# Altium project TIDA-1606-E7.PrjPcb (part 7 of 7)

## Sheet TIDA-1606-Aux-Supply-E7.SchDoc
size 431 x 279 mm; Date: Not shown in title block; ApprovedBy: Not shown in title block; CheckedBy: Not shown in title block; Author: Not shown in title block; CompanyName: Not shown in title block; Engineer: Not shown in title block; Organization: Not shown in title block; Address1: Not shown in title block; Address2: Not shown in title block; Address3: Not shown in title block; Address4: Not shown in title block; DocumentNumber: 3; Revision: Use project parameter SCH_Rev; SheetNumber: 3; SheetTotal: 16; PageSetup: Record=PageOptions¦CenterHorizontal=True¦CenterVertical=True¦PrintScale=1.00¦XCorrection=1.00¦YCorrection=1.00¦PrintKind=0¦BorderSize=5000000¦LeftOffset=0¦BottomOffset=0¦Orientation=2¦PaperLength=1000¦PaperWidth=1000¦Scale=100¦PaperSource=15¦PrintQuality=600¦MediaType=1¦DitherType=10¦PaperKind=Letter¦PrintScaleMode=1
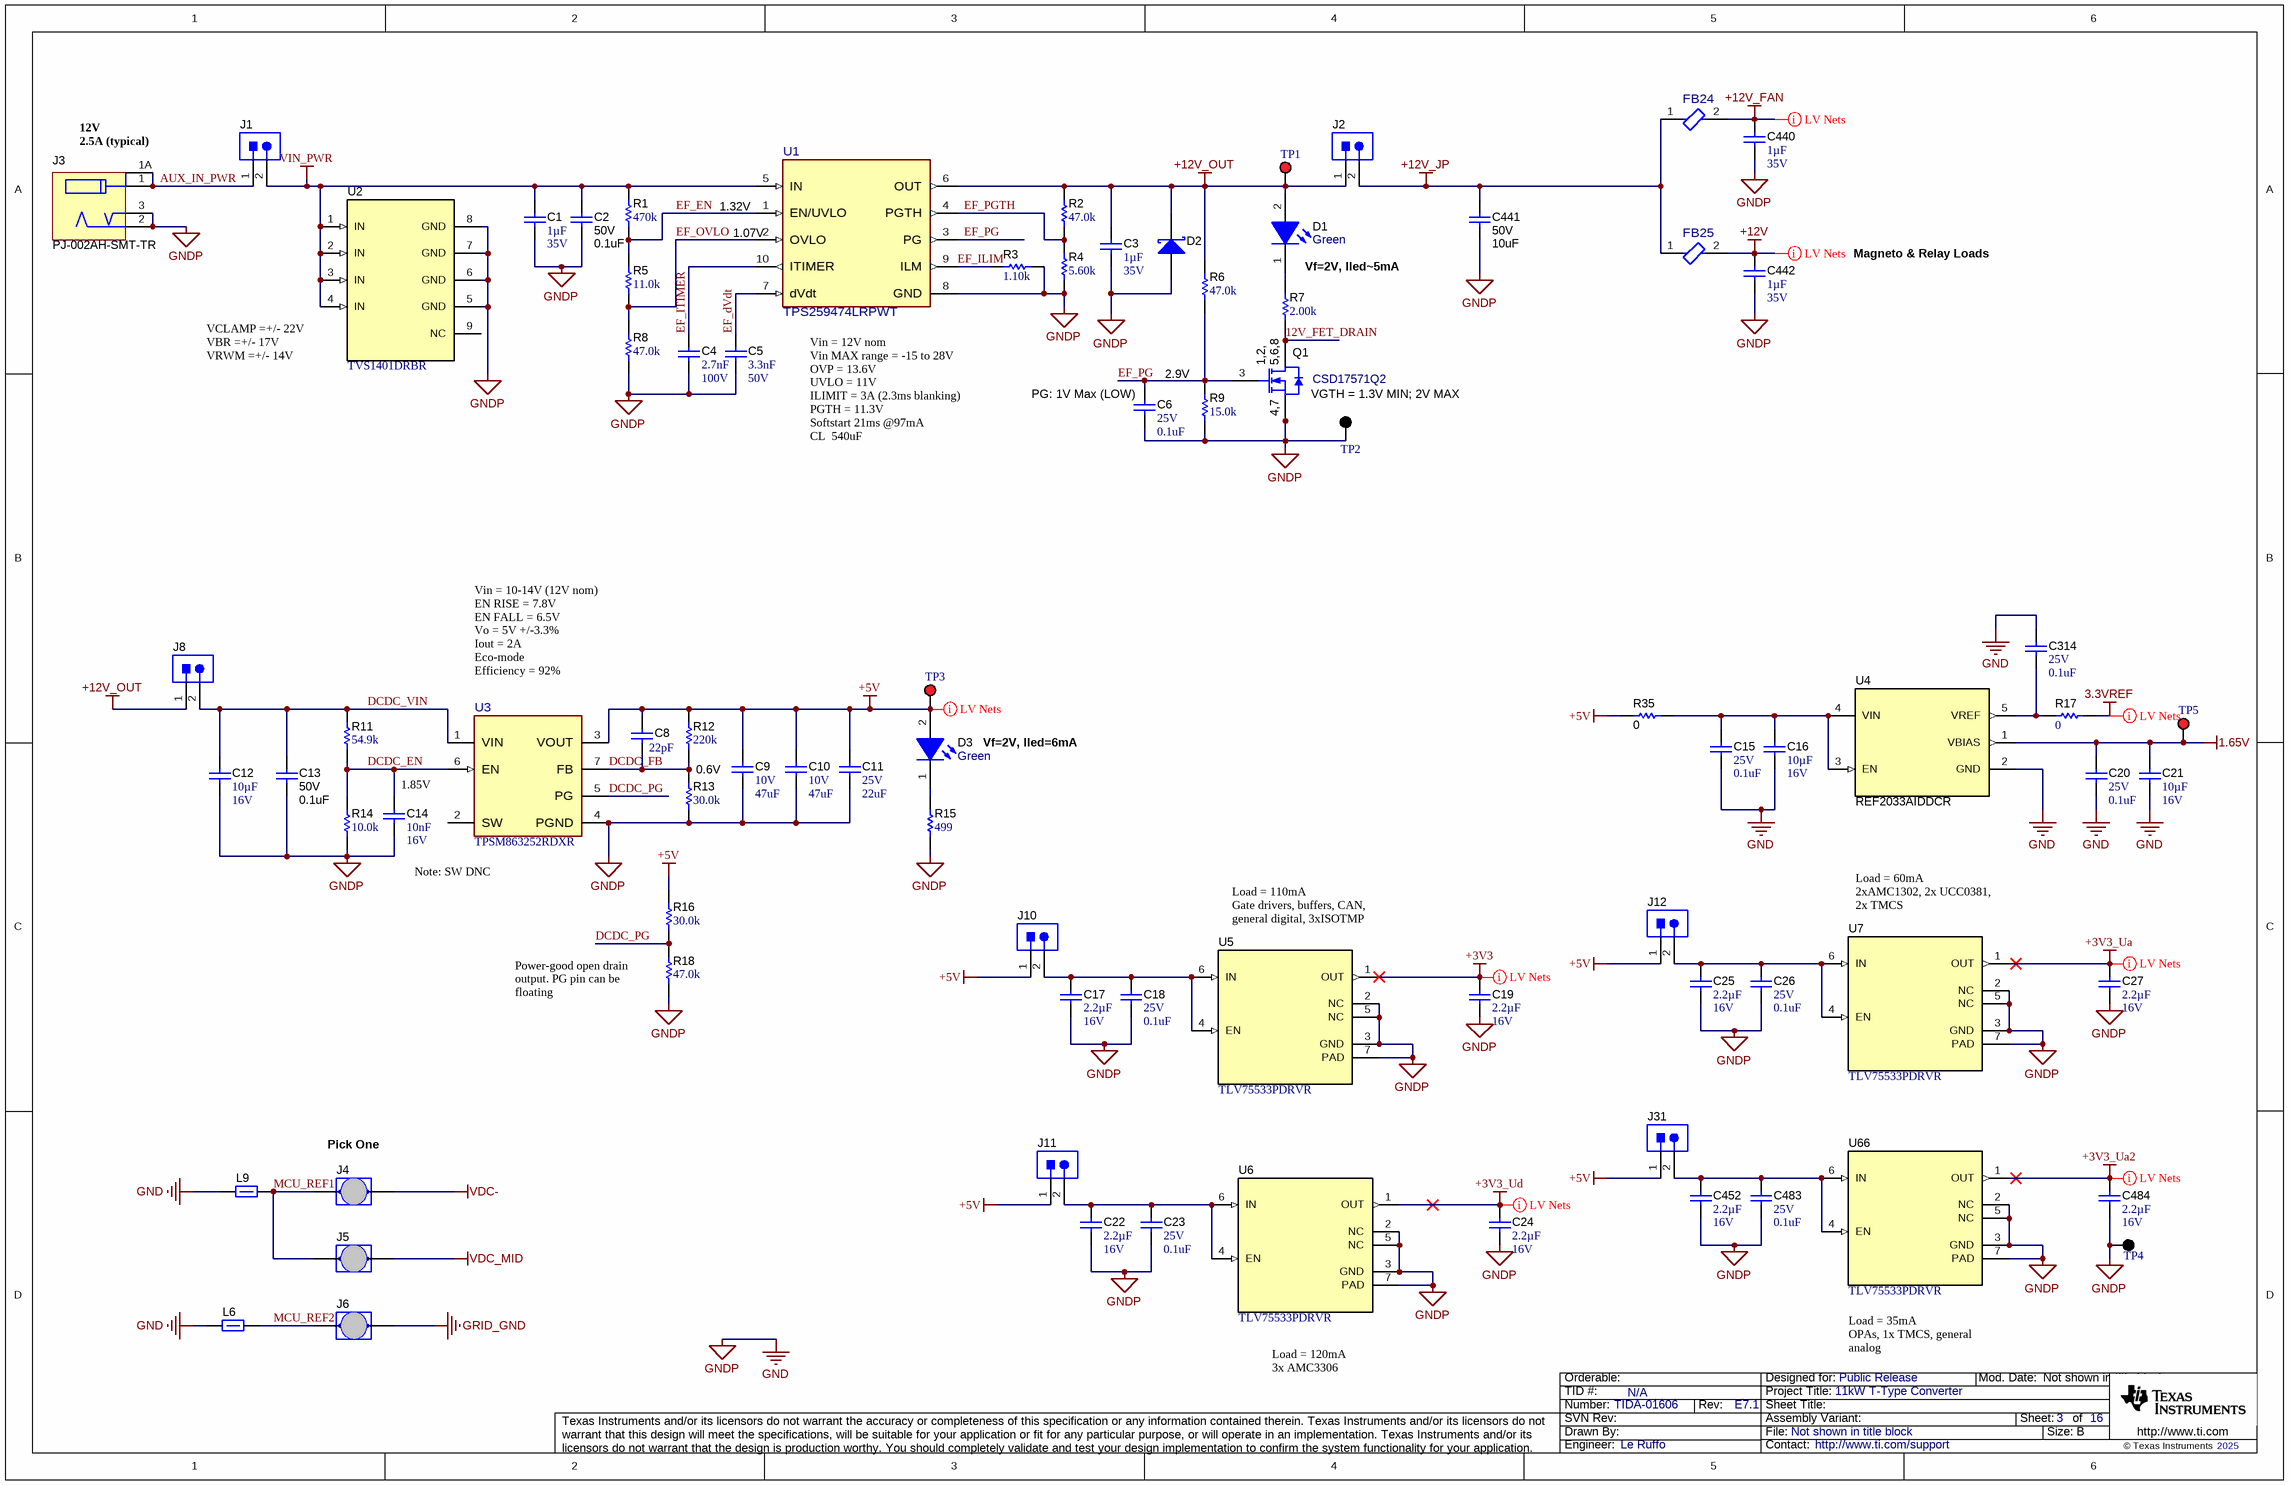
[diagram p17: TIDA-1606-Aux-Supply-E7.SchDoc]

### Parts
C1  Cap_F: 1µF  VDC_V: 35V  [0603]  (hidden comment: C1608X7R1V105K080AC)
C2  VDC_V: 50V  ValueDisplayed: 0.1uF  [0402S]  (hidden comment: GCM155R71H104KE02D)
C3  Cap_F: 1µF  VDC_V: 35V  [0603]  (hidden comment: C1608X7R1V105K080AC)
C4  Cap_F: 2.7nF  VDC_V: 100V  [0603]  (hidden comment: GRM188R72A272KA01D)
C5  Cap_F: 3.3nF  VDC_V: 50V  [0603]  (hidden comment: C0603X332K5RACTU)
C6  VDC_V: 25V  ValueDisplayed: 0.1uF  [0402L]  (hidden comment: GRM155R71E104KE14D)
C8  ValueDisplayed: 22pF  [0603]  (hidden comment: GRM1885C2A220JA01D)
C9  VDC_V: 10V  ValueDisplayed: 47uF  [1210_270]  (hidden comment: GRM32ER71A476KE15L)
C10  VDC_V: 10V  ValueDisplayed: 47uF  [1210_270]  (hidden comment: GRM32ER71A476KE15L)
C11  VDC_V: 25V  ValueDisplayed: 22uF  [1210_270]  (hidden comment: GRM32ER71E226KE15L)
C12  Cap_F: 10µF  VDC_V: 16V  [0805_HV]  (hidden comment: EMK212BB7106KG-T)
C13  VDC_V: 50V  ValueDisplayed: 0.1uF  [0402L]  (hidden comment: GCM155R71H104KE02D)
C14  Cap_F: 10nF  VDC_V: 16V  [0603]  (hidden comment: C0603C103K4RACTU)
C15  VDC_V: 25V  ValueDisplayed: 0.1uF  [0402L]  (hidden comment: GRM155R71E104KE14D)
C16  Cap_F: 10µF  VDC_V: 16V  [0805_HV]  (hidden comment: EMK212BB7106KG-T)
C17  Cap_F: 2.2µF  VDC_V: 16V  [0603]  (hidden comment: EMK107BB7225KA-T)
C18  VDC_V: 25V  ValueDisplayed: 0.1uF  [0402L]  (hidden comment: GRM155R71E104KE14D)
C19  Cap_F: 2.2µF  VDC_V: 16V  [0603]  (hidden comment: EMK107BB7225KA-T)
C20  VDC_V: 25V  ValueDisplayed: 0.1uF  [0402L]  (hidden comment: GRM155R71E104KE14D)
C21  Cap_F: 10µF  VDC_V: 16V  [0805_HV]  (hidden comment: EMK212BB7106KG-T)
C22  Cap_F: 2.2µF  VDC_V: 16V  [0603]  (hidden comment: EMK107BB7225KA-T)
C23  VDC_V: 25V  ValueDisplayed: 0.1uF  [0402L]  (hidden comment: GRM155R71E104KE14D)
C24  Cap_F: 2.2µF  VDC_V: 16V  [0603]  (hidden comment: EMK107BB7225KA-T)
C25  Cap_F: 2.2µF  VDC_V: 16V  [0603]  (hidden comment: EMK107BB7225KA-T)
C26  VDC_V: 25V  ValueDisplayed: 0.1uF  [0402L]  (hidden comment: GRM155R71E104KE14D)
C27  Cap_F: 2.2µF  VDC_V: 16V  [0603]  (hidden comment: EMK107BB7225KA-T)
C314  VDC_V: 25V  ValueDisplayed: 0.1uF  [0402L]  (hidden comment: GRM155R71E104KE14D)
C440  Cap_F: 1µF  VDC_V: 35V  [0603L]  (hidden comment: C1608X7R1V105K080AC)
C441  VDC_V: 50V  ValueDisplayed: 10uF  [1206_180L]  (hidden comment: CL31B106KBHNNNE)
C442  Cap_F: 1µF  VDC_V: 35V  [0603L]  (hidden comment: C1608X7R1V105K080AC)
C452  Cap_F: 2.2µF  VDC_V: 16V  [0603]  (hidden comment: EMK107BB7225KA-T)
C483  VDC_V: 25V  ValueDisplayed: 0.1uF  [0402L]  (hidden comment: GRM155R71E104KE14D)
C484  Cap_F: 2.2µF  VDC_V: 16V  [0603]  (hidden comment: EMK107BB7225KA-T)
D1  value Green  [WL-SMCW_GREEN]  (hidden comment: 150060VS75000)
D2  B330A-13-F  [SMA]  (value not drawn)
D3  value Green  [WL-SMCW_GREEN]  (hidden comment: 150060VS75000)
FB24  LCMGA160808T601RG  [FP-LCMGA160808T601RG_0603-MFG]  (value not drawn)
FB25  LCMGA160808T601RG  [FP-LCMGA160808T601RG_0603-MFG]  (value not drawn)
J1  61300211121  [WURTH_61300211121]  (value not drawn)
J2  61300211121  [WURTH_61300211121]  (value not drawn)
J3  PJ-002AH-SMT-TR  [CUI_PJ-002AH-SMT]
J4  999-11-113-10-000000  [Mill-Max_999-11-113-10-000000]  (value not drawn)
J5  999-11-113-10-000000  [Mill-Max_999-11-113-10-000000]  (value not drawn)
J6  999-11-113-10-000000  [Mill-Max_999-11-113-10-000000]  (value not drawn)
J8  61300211121  [WURTH_61300211121]  (value not drawn)
J10  61300211121  [WURTH_61300211121]  (value not drawn)
J11  61300211121  [WURTH_61300211121]  (value not drawn)
J12  61300211121  [WURTH_61300211121]  (value not drawn)
J31  61300211121  [WURTH_61300211121]  (value not drawn)
L6  782763102  [1206]  (value not drawn)
L9  782763102  [1206]  (value not drawn)
Q1  CSD17571Q2  [DQK0006C]
R1  ValueDisplayed: 470k  [0603]  (hidden comment: RC0603FR-07470KL)
R2  ValueDisplayed: 47.0k  [0603]  (hidden comment: RC0603FR-0747KL)
R3  ValueDisplayed: 1.10k  [0603]  (hidden comment: RC0603FR-071K1L)
R4  ValueDisplayed: 5.60k  [0603]  (hidden comment: RC0603FR-075K6L)
R5  ValueDisplayed: 11.0k  [0603]  (hidden comment: RC0603FR-0711KL)
R6  ValueDisplayed: 47.0k  [0603]  (hidden comment: RC0603FR-0747KL)
R7  ValueDisplayed: 2.00k  [0603]  (hidden comment: RC0603FR-072KL)
R8  ValueDisplayed: 47.0k  [0603]  (hidden comment: RC0603FR-0747KL)
R9  ValueDisplayed: 15.0k  [0603]  (hidden comment: RC0603FR-0715KL)
R11  ValueDisplayed: 54.9k  [0603]  (hidden comment: RC0603FR-0754K9L)
R12  ValueDisplayed: 220k  [0603]  (hidden comment: RC0603FR-07220KL)
R13  ValueDisplayed: 30.0k  [0603]  (hidden comment: RC0603FR-0730KL)
R14  ValueDisplayed: 10.0k  [0603]  (hidden comment: RG1608P-103-B-T5)
R15  ValueDisplayed: 499  [0603]  (hidden comment: CRCW0603499RFKEAC)
R16  ValueDisplayed: 30.0k  [0603]  (hidden comment: RC0603FR-0730KL)
R17  ValueDisplayed: 0  [0603]  (hidden comment: RC0603JR-070RL)
R18  ValueDisplayed: 47.0k  [0603]  (hidden comment: RC0603FR-0747KL)
R35  ValueDisplayed: 0  [0603L]  (hidden comment: RCS06030000Z0EA)
TP1  5010  [Keystone5010]  (value not drawn)
TP2  5011  [Keystone5011]  (value not drawn)
TP3  5010  [Keystone5010]  (value not drawn)
TP4  5011  [Keystone5011]  (value not drawn)
TP5  5000  [Keystone5000]  (value not drawn)
U1  TPS259474LRPWT  [RPW0010A-MFG]
U2  TVS1401DRBR  [DRB0008A]
U3  TPSM863252RDXR  [RDX0007A-MFG]
U4  REF2033AIDDCR  [DDC0005A_N]
U5  TLV75533PDRVR  [DRV0006A]
U6  TLV75533PDRVR  [DRV0006A]
U7  TLV75533PDRVR  [DRV0006A]
U66  TLV75533PDRVR  [DRV0006A]

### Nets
1.65V: C20.1 C21.2 TP5.1 U4.1(VBIAS)
3.3VREF: R17.1
+3V3: C19.1 U5.1(OUT)
+3V3_Ua: C27.1 U7.1(OUT)
+3V3_Ua2: C484.1 U66.1(OUT)
+3V3_Ud: C24.1 U6.1(OUT)
+5V: C8.1 C9.1 C10.1 C11.1 D3.2(A) J10.1 J11.1 J12.1 J31.1 R12.2 R16.2 R35.2 TP3.1 U3.3(VOUT)
+12V: C442.1 FB25.2
+12V_FAN: C440.1 FB24.2
+12V_JP: C441.1 FB24.1 FB25.1 J2.2
+12V_OUT: C3.1 D1.2(A) D2.1(K) J2.1 J8.1 R2.2 R6.2 TP1.1 U1.6(OUT)
GND: C1.2 C2.2 C3.2 C4.2 C5.2 C6.2 C9.2 C10.2 C11.2 C12.2 C13.1 C14.2 C15.2 C16.2 C17.2 C18.2 C19.2 C20.2 C21.1 C22.2 C23.2 C24.2 C25.2 C26.2 C27.2 C314.1 C440.2 C441.2 C442.2 C452.2 C483.2 C484.2 D2.2(A) J3.2 J3.3 L6.1 L9.1 Q1.4(S) Q1.7(S) R3.1 R4.1 R8.1 R9.1 R13.1 R14.2 R15.1 R18.1 TP2.1 TP4.1 U1.8(GND) U2.5(GND) U2.6(GND) U2.7(GND) U2.8(GND) U3.4(PGND) U4.2(GND) U5.2(NC) U5.3(GND) U5.5(NC) U5.7(PAD) U6.2(NC) U6.3(GND) U6.5(NC) U6.7(PAD) U7.2(NC) U7.3(GND) U7.5(NC) U7.7(PAD) U66.2(NC) U66.3(GND) U66.5(NC) U66.7(PAD)  [also labelled GNDP]
GRID_GND: J6.2
VDC-: J4.2
VDC_MID: J5.2
VIN_PWR: C1.1 C2.1 J1.2 R1.2 U1.5(IN) U2.1(IN) U2.2(IN) U2.3(IN) U2.4(IN)
12V_FET_DRAIN: Q1.1(D) Q1.2(D) Q1.5(D) Q1.6(D) Q1.8(D) R7.1
AUX_IN_PWR: J1.1 J3.1 J3.1A
DCDC_EN: C14.1 R11.1 R14.1 U3.6(EN)
DCDC_FB: C8.2 R12.1 R13.2 U3.7(FB)
DCDC_PG: R16.1 R18.2 U3.5(PG)
DCDC_VIN: C12.1 C13.2 J8.2 R11.2 U3.1(VIN)
EF_dVdt: C5.1 U1.7(dVdt)
EF_EN: R1.1 R5.2 U1.1(EN/UVLO)
EF_ILIM: R3.2 U1.9(ILM)
EF_ITIMER: C4.1 U1.10(ITIMER)
EF_OVLO: R5.1 R8.2 U1.2(OVLO)
EF_PG: C6.1 Q1.3(G) R6.1 R9.2 U1.3(PG)
EF_PGTH: R2.1 R4.2 U1.4(PGTH)
MCU_REF1: J4.1 J5.1 L9.2
MCU_REF2: J6.1 L6.2
NetC15_1: C15.1 C16.1 R35.1 U4.3(EN) U4.4(VIN)
NetC17_1: C17.1 C18.1 J10.2 U5.4(EN) U5.6(IN)
NetC22_1: C22.1 C23.1 J11.2 U6.4(EN) U6.6(IN)
NetC25_1: C25.1 C26.1 J12.2 U7.4(EN) U7.6(IN)
NetC314_2: C314.2 R17.2 U4.5(VREF)
NetC452_1: C452.1 C483.1 J31.2 U66.4(EN) U66.6(IN)
NetD1_1: D1.1(K) R7.2
NetD3_1: D3.1(K) R15.2

Not connected (* = marked no-connect by the designer): U2 9(NC); U3 2(SW)

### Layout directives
net class LV Nets: 3.3VREF, +3V3, +3V3_Ua, +3V3_Ua2, +3V3_Ud, +5V, +12V, +12V_FAN

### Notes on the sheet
- (near J3) 12V
  2.5A (typical)
- (near U1) 1.32V
- (near U1) 1.07V
- Vf=2V, Iled~5mA
- Magneto & Relay Loads
- (near U2) VCLAMP =+/- 22V
  VBR =+/- 17V
  VRWM =+/- 14V
- (near U1) Vin = 12V nom
  Vin MAX range = -15 to 28V
  OVP = 13.6V
  UVLO = 11V
  ILIMIT = 3A (2.3ms blanking)
  PGTH = 11.3V
  Softstart 21ms @97mA
  CL  540uF
- (near C6) PG: 1V Max (LOW)
- 2.9V
- VGTH = 1.3V MIN; 2V MAX
- Vin = 10-14V (12V nom)
  EN RISE = 7.8V
  EN FALL = 6.5V
  Vo = 5V +/-3.3%
  Iout = 2A
  Eco-mode
  Efficiency = 92%
- 0.6V
- Vf=2V, Iled=6mA
- (near C14) 1.85V
- Note: SW DNC
- (near U5) Load = 110mA
  Gate drivers, buffers, CAN, general digital, 3xISOTMP
- (near U7) Load = 60mA
  2xAMC1302, 2x UCC0381, 2x TMCS
- Power-good open drain output. PG pin can be floating
- (near J4) Pick One
- Load = 120mA
  3x AMC3306
- Load = 35mA
  OPAs, 1x TMCS, general analog

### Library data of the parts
C1 C3 = CMP-0007052-4: CAP, CERM, 1 uF, 35 V, +/- 10%, X7R, 0603; Manufacturer: TDK; TaMin_C: -55°C; Polarized: N; SizeAreaWB_mm2: 4.68; Value1: Unknown; U/M: EA; Value: 1uF; TaMax_C: 125°C; SizeZ_mm: 1; SizeX_mm: 1.6; SizeY_mm: 0.8; SizeArea_mm2: 1.28; AEC Category: Q200
C2 C13 = CMP-0006356-2: CAP, CERM, 0.1 uF, 50 V, +/- 10%, X7R, AEC-Q200 Grade 1, 0402; Manufacturer: MuRata; TaMin_C: -55°C; Polarized: N; SizeAreaWB_mm2: 3; Value1: Unknown; U/M: EA; Value: 0.1uF; TaMax_C: 125°C; SizeZ_mm: 0.6; SizeX_mm: 1; SizeY_mm: 0.5; Cap_Case: 0402; AEC Qualified: Y; Cap_F: 100nF; AEC Category: Q200
C4 = CMP-0007477-4: CAP, CERM, 2700 pF, 100 V, +/- 10%, X7R, 0603; Manufacturer: MuRata; TaMin_C: -55°C; Polarized: N; SizeAreaWB_mm2: 4.68; Value1: Unknown; U/M: EA; Value: 2700pF; TaMax_C: 125°C; SizeZ_mm: 1; SizeX_mm: 1.6; SizeY_mm: 0.8; SizeArea_mm2: 1.28; AEC Category: Q200
C5 = CMP-0006985-4: CAP, CERM, 3300 pF, 50 V, +/- 10%, X7R, 0603; Manufacturer: Kemet; TaMin_C: -55°C; Polarized: N; SizeAreaWB_mm2: 4.68; Value1: Unknown; U/M: EA; Value: 3300pF; TaMax_C: 125°C; SizeZ_mm: 1; SizeX_mm: 1.6; SizeY_mm: 0.8; SizeArea_mm2: 1.28; AEC Category: Q200
C6 C15 C18 C20 C23 C26 C314 C483 = CMP-0006659-2: CAP, CERM, 0.1 uF, 25 V, +/- 10%, X7R, 0402; Manufacturer: MuRata; TaMin_C: -55°C; Polarized: N; SizeAreaWB_mm2: 3; Value1: Unknown; U/M: EA; Value: 0.1uF; TaMax_C: 125°C; SizeZ_mm: 0.6; SizeX_mm: 1; SizeY_mm: 0.5; Cap_Case: 0402; Cap_F: 100nF; AEC Category: Q200
C8 = CMP-0007255-4: CAP, CERM, 22 pF, 100 V, +/- 5%, C0G/NP0, 0603; Manufacturer: MuRata; TaMin_C: -55°C; Polarized: N; SizeAreaWB_mm2: 4.68; Value1: Unknown; U/M: EA; Value: 22pF; TaMax_C: 125°C; SizeZ_mm: 1; SizeX_mm: 1.6; SizeY_mm: 0.8; Value2: 100V; SizeArea_mm2: 1.28; AEC Category: Q200
C9 C10 = CMP-0009220-2: CAP, CERM, 47 uF, 10 V, +/- 10%, X7R, 1210; Manufacturer: MuRata; TaMin_C: -55°C; Polarized: N; SizeAreaWB_mm2: 14.7; Value1: Unknown; U/M: EA; Value: 47uF; TaMax_C: 125°C; SizeZ_mm: 2.7; SizeX_mm: 3.2; SizeY_mm: 2.5; Cap_Case: 1210; SizeArea_mm2: 8; Cap_F: 47µF; AEC Category: Q200
C11 = CMP-0009224-2: CAP, CERM, 22 uF, 25 V, +/- 10%, X7R, 1210; Manufacturer: MuRata; TaMin_C: -55°C; Polarized: N; SizeAreaWB_mm2: 14.7; Value1: Unknown; U/M: EA; Value: 22uF; TaMax_C: 125°C; SizeZ_mm: 2.7; SizeX_mm: 3.2; SizeY_mm: 2.5; Cap_Case: 1210; SizeArea_mm2: 8; Cap_F: 22µF; AEC Category: Q200
C12 C16 C21 = CMP-0085283-1: CAP, CERM, 10 µF, 16 V,+/- 10%, X7R, 0805; Manufacturer: Taiyo Yuden; TaMin_C: -55°C; AEC Qualified: N; U/M: EA; TaMax_C: 125°C; SizeAreaWB_mm2: 6.75; SizeZ_mm: 1.45; Value: 10uF; SizeY_mm: 1.25; SizeArea_mm2: 2.5; AEC Category: Q200; SizeX_mm: 2; Cap_Case: 0805
C14 = CMP-0006853-4: CAP, CERM, 0.01 uF, 16 V, +/- 10%, X7R, 0603; Manufacturer: Kemet; TaMin_C: -55°C; Polarized: N; SizeAreaWB_mm2: 4.68; Value1: Unknown; U/M: EA; Value: 0.01uF; TaMax_C: 125°C; SizeZ_mm: 1; SizeX_mm: 1.6; SizeY_mm: 0.8; SizeArea_mm2: 1.28; AEC Category: Q200
C17 C19 C22 C24 C25 C27 C452 C484 = CMP-0007121-4: CAP, CERM, 2.2 uF, 16 V, +/- 10%, X7R, 0603; Manufacturer: Taiyo Yuden; TaMin_C: -55°C; Polarized: N; SizeAreaWB_mm2: 4.68; Value1: Unknown; U/M: EA; Value: 2.2uF; TaMax_C: 125°C; SizeZ_mm: 1; SizeX_mm: 1.6; SizeY_mm: 0.8; SizeArea_mm2: 1.28; AEC Category: Q200
C440 C442 = CMP-0007052-4: CAP, CERM, 1 uF, 35 V, +/- 10%, X7R, 0603; Manufacturer: TDK; TaMin_C: -55°C; Polarized: N; SizeAreaWB_mm2: 4.68; Value1: Unknown; U/M: EA; Value: 1uF; TaMax_C: 125°C; SizeZ_mm: 1; SizeX_mm: 1.6; SizeY_mm: 0.8; Cap_Case: 0603; SizeArea_mm2: 1.28; AEC Category: Q200
C441 = CMP-0008802-2: CAP, CERM, 10 uF, 50 V, +/- 10%, X7R, 1206; Manufacturer: Samsung; TaMin_C: -55°C; Polarized: N; SizeAreaWB_mm2: 10.92; Value1: Unknown; U/M: EA; Value: 10uF; TaMax_C: 125°C; SizeZ_mm: 1.8; SizeX_mm: 3.2; SizeY_mm: 1.6; Cap_Case: 1206; SizeArea_mm2: 5.12; Cap_F: 10µF; AEC Category: Q200
D1 D3 = CMP-0002894-2: LED, Green, SMD; Manufacturer: Wurth Elektronik; Type: AlInGaP; Value2: 2V; Io_A: 20mA; Value1: W
D2 = CMP-0028350-2: Diode, Schottky, 30 V, 3 A, SMA; Manufacturer: Diodes Inc.; Io_A: 3A; SizeZ_mm: 2.87; SizeAreaWB_mm2: 37.3428; Value: 30V; TJmax_C: 125°C; Green_Lifecycle: Active; SizeY_mm: 2.92; Vf_V: 500mV; Green_REACh: Passed; SizeArea_mm2: 16.3228; AEC Category: Q101; Value2: 0.5V; SizeX_mm: 5.59; RJC_CperW: 25
FB24 FB25 = CMP-0124053-1: Ferrite Bead 600Ohm 0.9A 0.17Ohm Wirewound 2-Pin 0603 Paper T/R; Manufacturer: Taiyo Yuden; DCR_ohm: 0.17; Imax_A: 900mA; SizeZ_mm: 0.9mm; AEC Grade: Grade 1; AEC Qualified: Yes; Impedance At Frequency: 600Ω @ 100MHz; Tolerance_%: 25%
J1 J2 J8 J10-J12 J31 = CMP-0054794-2: Header, 2.54 mm, 2x1, Gold, TH; Manufacturer: Wurth Elektronik; Green_Lifecycle: Active; Green_REACh: Passed; Cert_UL: Y; Gender: Male; Pitch_mm: 2.54; Row_Count: 1; Shrouded: N
J3 = CMP-0075012-1: Power Jack, SMT; Manufacturer: CUI Inc.; Green_Lifecycle: Not Set; Green_REACh: Incomplete; CNHeader: False
J4-J6 = CMP-0055045-1: Shorting Jumper, 7.62mm, 2 Position, Gold, TH; Manufacturer: Mill-Max; CNHeader: FALSE; Gender: Male; Pitch_mm: 7.62; Cert_UL: Y
L6 L9 = CMP-0003288-1: Ferrite Bead, 1000 ohm @ 100 MHz, 1 A, 1206; Manufacturer: Wurth Elektronik; Ztyp@1GHz_Ohm: 133.171; ZTyp@100MHz_Ohm: 1k; SizeAreaWB_mm2: 10.92; DCR_ohm: 0.3; Value1: 0.3 ohm; Imax_A: 1A; SizeZ_mm: 1.35; SizeX_mm: 3.2; SizeY_mm: 1.6; SizeArea_mm2: 5.12
Q1 = CMP-0000585-1: MOSFET, N-CH, 30 V, 22 A, DQK0006C (WSON-6); Alternate Manufacturer: None; Manufacturer: Texas Instruments; SizeZ_mm: 0.8; ChType: N; Value2: 2.4 nC; Value1: 0.02; VdsMax_V: 30V; SizeX_mm: 2; Vgs_V: 20V; Value: 30V; Rdson45_ohm: 0.029; SizeArea_mm2: 4; AEC Category: Q101; IdsMax_A: 22A; SizeAreaWB_mm2: 9; U/M: EA; QgTyp_nC: 2.4
R1 = CMP-0023128-4: RES, 470 k, 1%, 0.1 W, 0603; Manufacturer: Yageo; Power_W: 100mW; TempCo: 100 ppm/C; Value: 470k; SizeX_mm: 1.6; SizeY_mm: 0.8; SizeZ_mm: 1; Value2: 0.1W; SizeArea_mm2: 1.28; AEC Qualified: N; VDC_V: 75V; AEC Category: Q200; SizeAreaWB_mm2: 4.68
R2 R6 R8 R18 = CMP-0023133-5: RES, 47.0 k, 1%, 0.1 W, 0603; Manufacturer: Yageo; Power_W: 100mW; TempCo: 100 ppm/C; Value_Code: 47k0; Value: 47.0k; Res_ohm: 47k; SizeX_mm: 1.6; SizeY_mm: 0.8; SizeZ_mm: 1; Value2: 0.1W; SizeArea_mm2: 1.28; AEC Qualified: N; VDC_V: 75V; AEC Category: Q200; SizeAreaWB_mm2: 4.68
R3 = CMP-0022870-5: RES, 1.10 k, 1%, 0.1 W, 0603; Manufacturer: Yageo; Power_W: 100mW; TempCo: 100 ppm/C; Value_Code: 1k10; Value: 1.10k; EIA_Code: E96; Res_ohm: 1.1k; SizeX_mm: 1.6; SizeY_mm: 0.8; SizeZ_mm: 1; Value2: 0.1W; SizeArea_mm2: 1.28; AEC Qualified: N; VDC_V: 75V; AEC Category: Q200; SizeAreaWB_mm2: 4.68
R4 = CMP-0023203-5: RES, 5.60 k, 1%, 0.1 W, 0603; Manufacturer: Yageo; Power_W: 100mW; TempCo: 100 ppm/C; Value_Code: 5k60; Value: 5.60k; Res_ohm: 5.6k; SizeX_mm: 1.6; SizeY_mm: 0.8; SizeZ_mm: 1; Value2: 0.1W; SizeArea_mm2: 1.28; AEC Qualified: N; VDC_V: 75V; AEC Category: Q200; SizeAreaWB_mm2: 4.68
R5 = CMP-0022763-5: RES, 11.0 k, 1%, 0.1 W, 0603; Manufacturer: Yageo; Power_W: 100mW; TempCo: 100 ppm/C; Value_Code: 11k0; Value: 11.0k; EIA_Code: E96; Res_ohm: 11k; SizeX_mm: 1.6; SizeY_mm: 0.8; SizeZ_mm: 1; Value2: 0.1W; SizeArea_mm2: 1.28; AEC Qualified: N; VDC_V: 75V; AEC Category: Q200; SizeAreaWB_mm2: 4.68
R7 = CMP-0023000-5: RES, 2.00 k, 1%, 0.1 W, 0603; Manufacturer: Yageo; Power_W: 100mW; TempCo: 100 ppm/C; Value_Code: 2k00; Value: 2.00k; EIA_Code: E96; Res_ohm: 2k; SizeX_mm: 1.6; SizeY_mm: 0.8; SizeZ_mm: 1; Value2: 0.1W; SizeArea_mm2: 1.28; AEC Qualified: N; VDC_V: 75V; AEC Category: Q200; SizeAreaWB_mm2: 4.68
R9 = CMP-0022816-5: RES, 15.0 k, 1%, 0.1 W, 0603; Manufacturer: Yageo; Power_W: 100mW; TempCo: 100 ppm/C; Value_Code: 15k0; Value: 15.0k; EIA_Code: E96; Res_ohm: 15k; SizeX_mm: 1.6; SizeY_mm: 0.8; SizeZ_mm: 1; Value2: 0.1W; SizeArea_mm2: 1.28; AEC Qualified: N; VDC_V: 75V; AEC Category: Q200; SizeAreaWB_mm2: 4.68
R11 = CMP-0023180-5: RES, 54.9 k, 1%, 0.1 W, 0603; Manufacturer: Yageo; Power_W: 100mW; TempCo: 100 ppm/C; Value_Code: 54k9; Value: 54.9k; EIA_Code: E96; SizeX_mm: 1.6; SizeY_mm: 0.8; SizeZ_mm: 1; Value2: 0.1W; SizeArea_mm2: 1.28; AEC Qualified: N; VDC_V: 75V; AEC Category: Q200; SizeAreaWB_mm2: 4.68
R12 = CMP-0022917-4: RES, 220 k, 1%, 0.1 W, 0603; Manufacturer: Yageo; Power_W: 100mW; TempCo: 100 ppm/C; Value: 220k; SizeX_mm: 1.6; SizeY_mm: 0.8; SizeZ_mm: 1; Value2: 0.1W; SizeArea_mm2: 1.28; AEC Qualified: N; VDC_V: 75V; AEC Category: Q200; SizeAreaWB_mm2: 4.68
R13 R16 = CMP-0023020-5: RES, 30.0 k, 1%, 0.1 W, 0603; Manufacturer: Yageo; Power_W: 100mW; TempCo: 100 ppm/C; Value_Code: 30k0; Value: 30.0k; Res_ohm: 30k; SizeX_mm: 1.6; SizeY_mm: 0.8; SizeZ_mm: 1; Value2: 0.1W; SizeArea_mm2: 1.28; AEC Qualified: N; VDC_V: 75V; AEC Category: Q200; SizeAreaWB_mm2: 4.68
R14 = CMP-0023404-3: RES, 10.0 k, 0.1%, 0.1 W, 0603; Manufacturer: Susumu Co Ltd; Power_W: 100mW; TempCo: 25 ppm/C; Value_Code: 10k0; U/M: EA; Value: 10.0k; EIA_Code: E192; Res_ohm: 10k; SizeX_mm: 1.6; SizeY_mm: 0.8; SizeZ_mm: 1; Value2: 0.1W; SizeArea_mm2: 1.28; VDC_V: 75V; AEC Category: Q200
R15 = CMP-0082532-1: RES, 499, 1%, 0.1 W, 0603; Manufacturer: Vishay-Dale; Power_W: 100mW; TempCo: 100 ppm/C; SizeAreaWB_mm2: 4.68; Value_Code: 499R; Value: 499; EIA_Code: E96; SizeX_mm: 1.6; SizeY_mm: 0.8; SizeZ_mm: 1; Value2: 0.1W; SizeArea_mm2: 1.28; AEC Qualified: N; VDC_V: 75V; AEC Category: Q200
R17 = CMP-0025885-5: RES, 0, 5%, 0.1 W, 0603; Manufacturer: Yageo; Power_W: 100mW; TempCo: 200 ppm/C; Value_Code: 0000; Value: 0; EIA_Code: E24; SizeX_mm: 1.6; SizeZ_mm: 1; Value2: 0.1W; SizeArea_mm2: 1.28; AEC Qualified: N; VDC_V: 75V; AEC Category: Q200; SizeY_mm: 0.8; SizeAreaWB_mm2: 4.68
R35 = CMP-0081973-1: RES, 0, 0%, 0.25 W, AEC-Q200 Grade 0, 0603; Manufacturer: Vishay-Dale; SizeAreaWB_mm2: 4.68; SizeArea_mm2: 1.28; AEC Qualified: Y; AEC Category: Q200; Value: 0; SizeZ_mm: 1; SizeY_mm: 0.8; Power_W: 250mW; Value2: 0.25W; SizeX_mm: 1.6
TP1 TP3 = CMP-0055147-2: Test Point, Multipurpose, Red, TH; Manufacturer: Keystone Electronics; CT: TRUE; ContactFinish: Silver; Green_Lifecycle: Active; CNHeader: FALSE; Green_REACh: Passed
TP2 TP4 = CMP-0055148-2: Test Point, Multipurpose, Black, TH; Manufacturer: Keystone Electronics; CNHeader: FALSE; ContactFinish: Silver; Green_REACh: Passed; Green_Lifecycle: Active; CT: TRUE
TP5 = CMP-0055137-2: Test Point, Miniature, Red, TH; Manufacturer: Keystone Electronics; CNHeader: FALSE; ContactFinish: Silver; CT: TRUE; Green_Lifecycle: Active; Green_REACh: Passed
U1 = CMP-0088329-1: 2.7- 23V, 5.5 A, 28 mΩ Reverse Current Blocking eFuse with Input Reverse Polarity Protection; Manufacturer: Texas Instruments; AEC Qualified: No; Nominal Supply Current: 0.5-6A; Threshold Voltage: 1.2/1.1V; Standoff Height: 0mm; Number Of Rails Monitored: 1; SizeZ_mm: 1mm; Min Supply Voltage: 2.7V; Reset Type: Active Low; TJmax_C: +125°C; Output Voltage: 42V
U2 = CMP-0083940-3: 14 V Bidirectional Flat-Clamp Surge Protection Device, DRB0008A (VSON-8); Alternate PartNumber: TVS1401DRBT; Alternate Manufacturer: Texas Instruments; CompType: IC; SizeAreaWB_mm2: 16.0; SizeZ_mm: 1.0; SizeY_mm: 3.0; AEC Category: Q200; SizeArea_mm2: 9.0; AEC Qualified: N
U3 = CMP-0034908-2: 3V to 16 V Input, 3-A Synchronous Step-Down Voltage Regulator Module, QFN-FCMOD7; Manufacturer: Texas Instruments; SizeZ_mm: 2.1mm; AEC Qualified: No; Max Duty Cycle: 95%; Max Supply Voltage: 17V; Nominal Supply Current: 100-400uA; Number Of Outputs: 1; Output Type: AdjustableProgrammable; Output Voltage: 0.6-10V; Standoff Height: 0mm; Switching Frequency: 1.2MHz; Switching Topology: Buck; TJmax_C: +125°C; AEC Category: Q200; CompType: IC
U4 = CMP-0066190-1: Low-Drift, Low-Power, Dual-Output VREF and VREF/2 Voltage Reference, DDC0005A (SOT-23-T-5); Alternate PartNumber: REF2033AIDDCT; Manufacturer: Texas Instruments; CompType: IC; U/M: EA; SizeArea_mm2: 8.12; SizeAreaWB_mm2: 14.82; SizeX_mm: 2.8; SizeY_mm: 2.9; SizeZ_mm: 1.1
U5-U7 U66 = CMP-0013427-7: 500mA LDO, DRV0006A (WSON-6); Manufacturer: Texas Instruments; SizeX_mm: 2; CompType: IC; SizeZ_mm: 0.8; SizeArea_mm2: 4; SizeAreaWB_mm2: 9; U/M: EA

## Sheet TIDA-1606-Hardware-E7.SchDoc
size 431 x 279 mm; Date: Not shown in title block; ApprovedBy: Not shown in title block; CheckedBy: Not shown in title block; Author: Not shown in title block; CompanyName: Not shown in title block; Engineer: Not shown in title block; Organization: Not shown in title block; Address1: Not shown in title block; Address2: Not shown in title block; Address3: Not shown in title block; Address4: Not shown in title block; DocumentNumber: 2; Revision: Use project parameter SCH_Rev; SheetNumber: 2; SheetTotal: 16; PageSetup: Record=PageOptions¦CenterHorizontal=True¦CenterVertical=True¦PrintScale=1.00¦XCorrection=1.00¦YCorrection=1.00¦PrintKind=0¦BorderSize=5000000¦LeftOffset=0¦BottomOffset=0¦Orientation=2¦PaperLength=1000¦PaperWidth=1000¦Scale=100¦PaperSource=15¦PrintQuality=600¦MediaType=1¦DitherType=10¦PaperKind=Letter¦PrintScaleMode=1
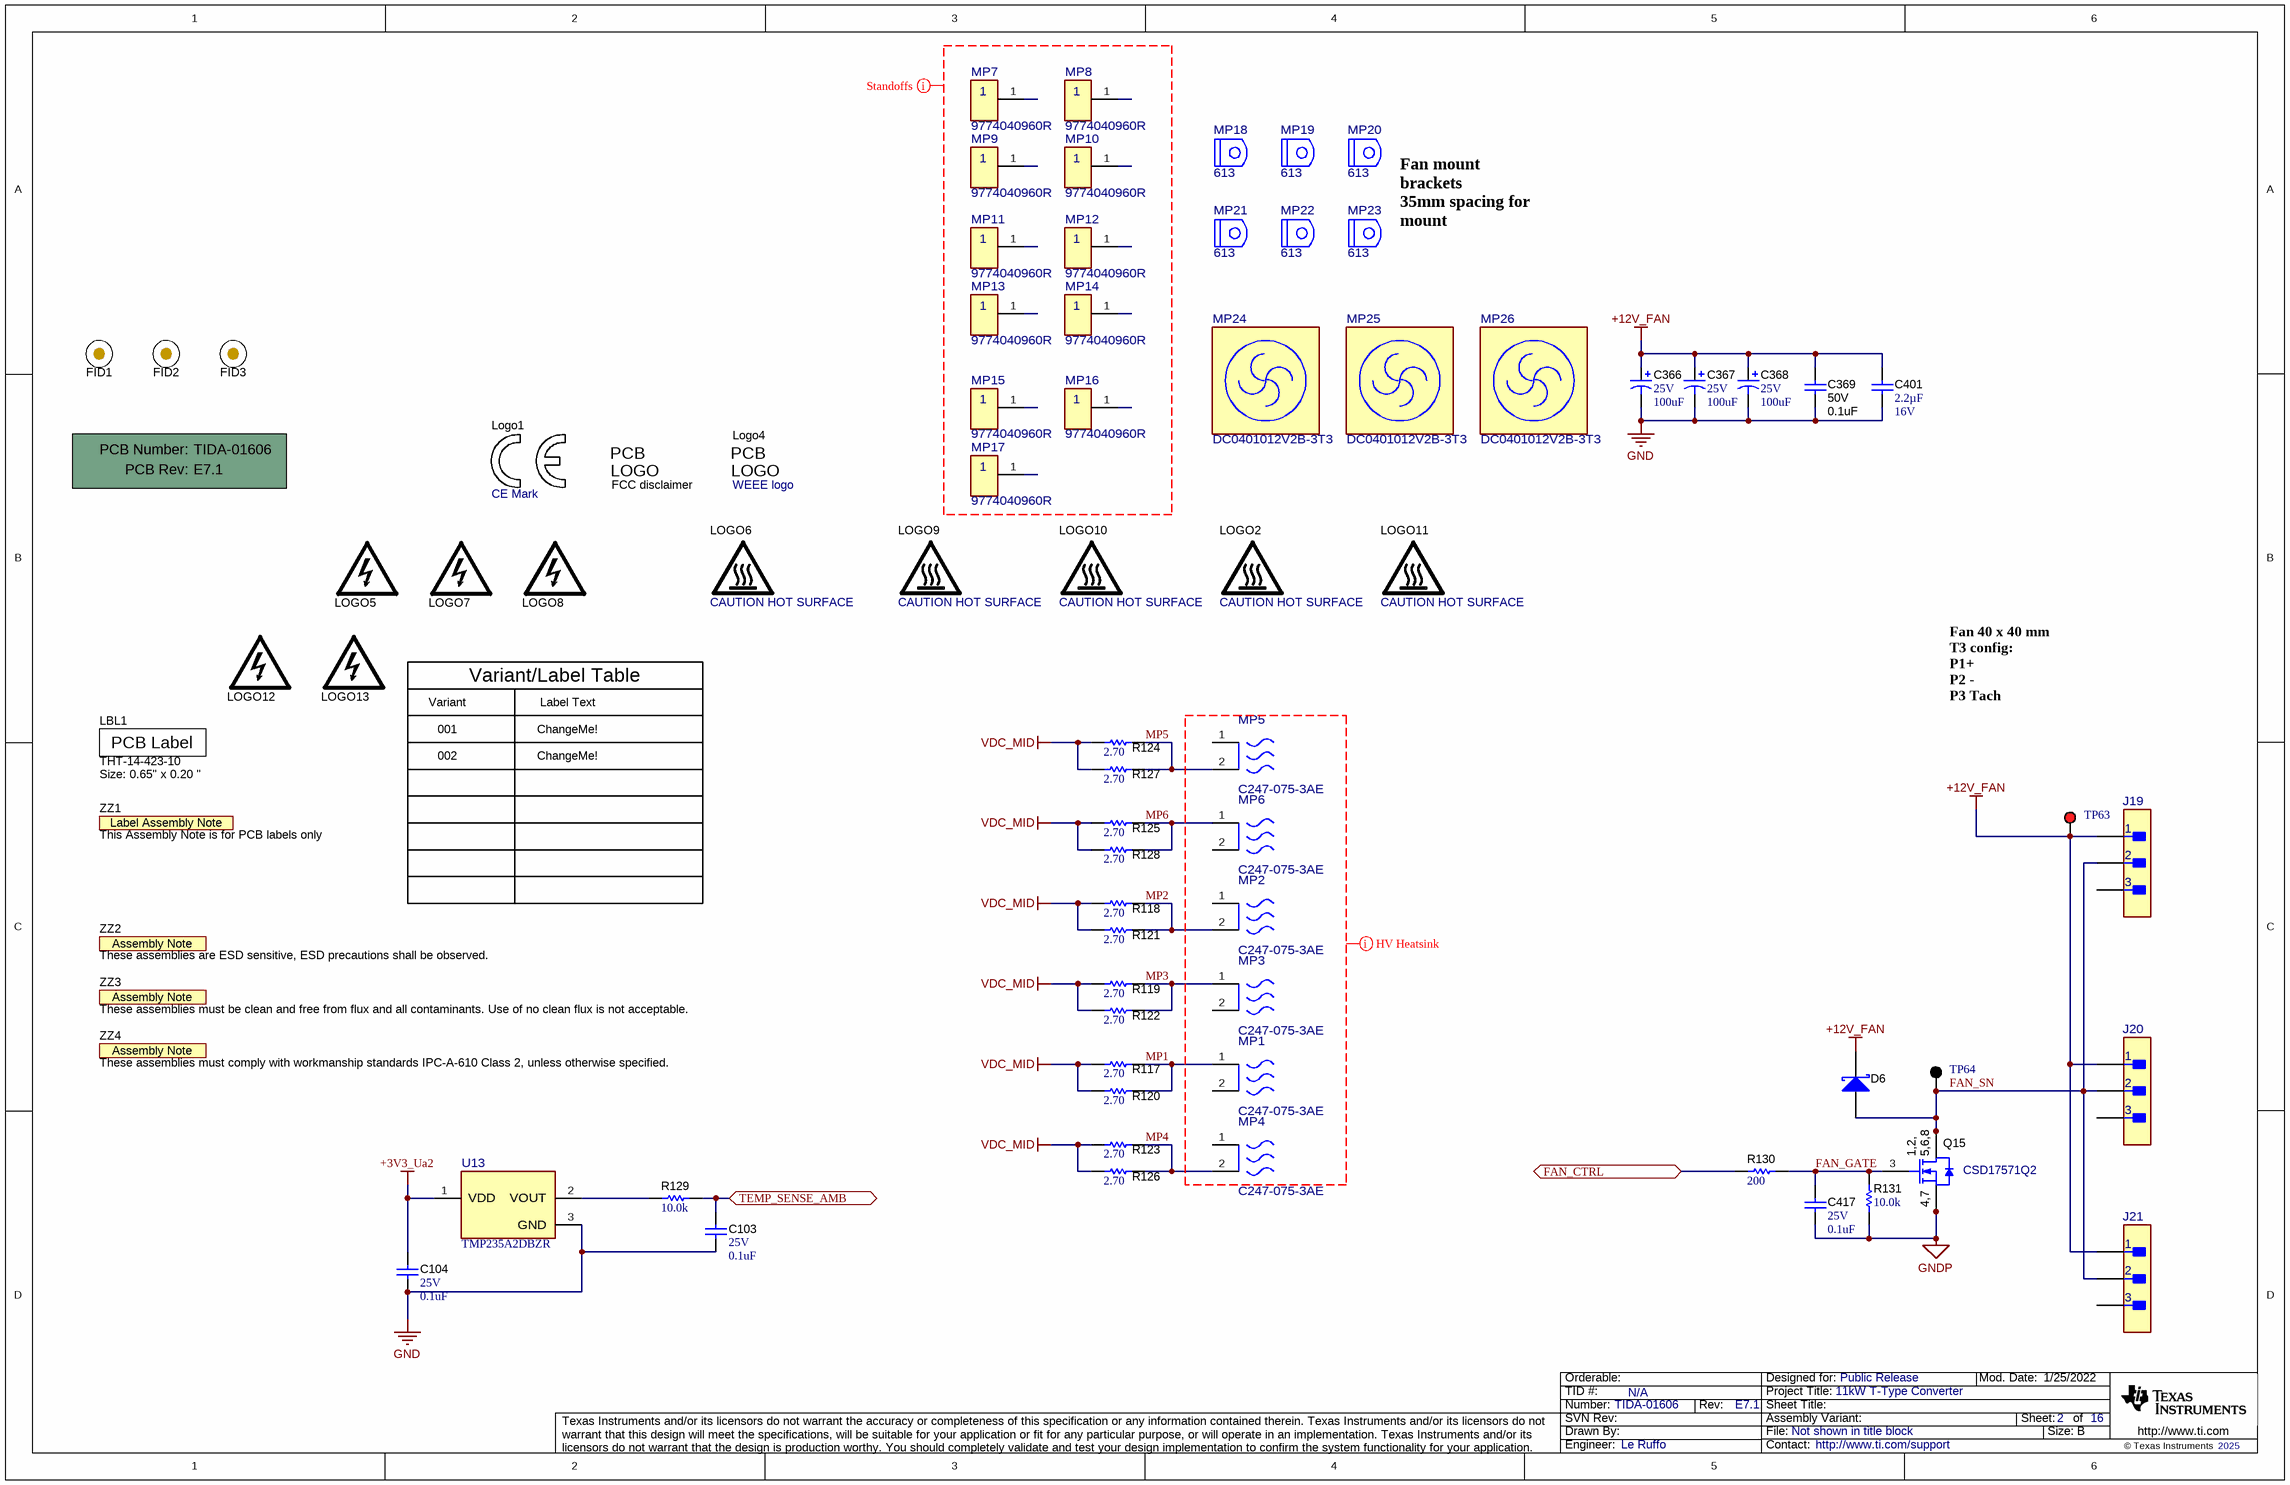
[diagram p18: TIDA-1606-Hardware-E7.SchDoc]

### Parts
!PCB1  Printed Circuit Board  (value not drawn)  (mechanical)
C103  VDC_V: 25V  ValueDisplayed: 0.1uF  [0402L]  (hidden comment: GRM155R71E104KE14D)
C104  VDC_V: 25V  ValueDisplayed: 0.1uF  [0402L]  (hidden comment: GRM155R71E104KE14D)
C366  VDC_V: 25V  ValueDisplayed: 100uF  [FM_630x1120]  (hidden comment: EEU-FM1E101)
C367  VDC_V: 25V  ValueDisplayed: 100uF  [FM_630x1120]  (hidden comment: EEU-FM1E101)
C368  VDC_V: 25V  ValueDisplayed: 100uF  [FM_630x1120]  (hidden comment: EEU-FM1E101)
C369  VDC_V: 50V  ValueDisplayed: 0.1uF  [0402S]  (hidden comment: GCM155R71H104KE02D)
C401  Cap_F: 2.2µF  VDC_V: 16V  [0603]  (hidden comment: EMK107BB7225KA-T)
C417  VDC_V: 25V  ValueDisplayed: 0.1uF  [0402L]  (hidden comment: GRM155R71E104KE14D)
D6  B160-13-F  [SMA]  (value not drawn)
FID1  Fiducial  [Fiducial10-20]  (value not drawn)
FID2  Fiducial  [Fiducial10-20]  (value not drawn)
FID3  Fiducial  [Fiducial10-20]  (value not drawn)
J19  0022111031  [FP-0022111031_HDR3-MFG]  (value not drawn)
J20  0022111031  [FP-0022111031_HDR3-MFG]  (value not drawn)
J21  0022111031  [FP-0022111031_HDR3-MFG]  (value not drawn)
LBL1  THT-14-423-10  Note: Size: 0.65" x 0.20 "  [Label_650x200]
Logo1  CE Mark  [CE_Mark_5mm]  (no BOM)
LOGO2  CAUTION HOT SURFACE  [IEC_HotSurface_Medium]  (no BOM)
Logo3  FCC disclaimer  [FCC_disclaimer]  (no BOM)
Logo4  WEEE logo  [WEEE_Minimum]  (no BOM)
LOGO5  DANGER HIGH VOLTAGE  [IEC_HighVoltage_Medium]  (value not drawn)  (no BOM)
LOGO6  CAUTION HOT SURFACE  [IEC_HotSurface_Medium]  (no BOM)
LOGO7  DANGER HIGH VOLTAGE  [IEC_HighVoltage_Medium]  (value not drawn)  (no BOM)
LOGO8  DANGER HIGH VOLTAGE  [IEC_HighVoltage_Medium]  (value not drawn)  (no BOM)
LOGO9  CAUTION HOT SURFACE  [IEC_HotSurface_Medium]  (no BOM)
LOGO10  CAUTION HOT SURFACE  [IEC_HotSurface_Medium]  (no BOM)
LOGO11  CAUTION HOT SURFACE  [IEC_HotSurface_Medium]  (no BOM)
LOGO12  DANGER HIGH VOLTAGE  [IEC_HighVoltage_Medium]  (value not drawn)  (no BOM)
LOGO13  DANGER HIGH VOLTAGE  [IEC_HighVoltage_Medium]  (value not drawn)  (no BOM)
MP1  C247-075-3AE  [FP-C247-075-3AE_PTH_HTSNK_75MM0_18MM0-MFG]
MP2  C247-075-3AE  [FP-C247-075-3AE_PTH_HTSNK_75MM0_18MM0-MFG]
MP3  C247-075-3AE  [FP-C247-075-3AE_PTH_HTSNK_75MM0_18MM0-MFG]
MP4  C247-075-3AE  [FP-C247-075-3AE_PTH_HTSNK_75MM0_18MM0-MFG]
MP5  C247-075-3AE  [FP-C247-075-3AE_PTH_HTSNK_75MM0_18MM0-MFG]
MP6  C247-075-3AE  [FP-C247-075-3AE_PTH_HTSNK_75MM0_18MM0-MFG]
MP7  9774040960R  [FP-9774040960R_ROUND_SPACER_6MM0-MFG]
MP8  9774040960R  [FP-9774040960R_ROUND_SPACER_6MM0-MFG]
MP9  9774040960R  [FP-9774040960R_ROUND_SPACER_6MM0-MFG]
MP10  9774040960R  [FP-9774040960R_ROUND_SPACER_6MM0-MFG]
MP11  9774040960R  [FP-9774040960R_ROUND_SPACER_6MM0-MFG]
MP12  9774040960R  [FP-9774040960R_ROUND_SPACER_6MM0-MFG]
MP13  9774040960R  [FP-9774040960R_ROUND_SPACER_6MM0-MFG]
MP14  9774040960R  [FP-9774040960R_ROUND_SPACER_6MM0-MFG]
MP15  9774040960R  [FP-9774040960R_ROUND_SPACER_6MM0-MFG]
MP16  9774040960R  [FP-9774040960R_ROUND_SPACER_6MM0-MFG]
MP17  9774040960R  [FP-9774040960R_ROUND_SPACER_6MM0-MFG]
MP18  613  [FP-613_MNT_BRACKET-MFG]
MP19  613  [FP-613_MNT_BRACKET-MFG]
MP20  613  [FP-613_MNT_BRACKET-MFG]
MP21  613  [FP-613_MNT_BRACKET-MFG]
MP22  613  [FP-613_MNT_BRACKET-MFG]
MP23  613  [FP-613_MNT_BRACKET-MFG]
MP24  DC0401012V2B-3T3  [FP-DC0401012V2B_FAN-MFG]
MP25  DC0401012V2B-3T3  [FP-DC0401012V2B_FAN-MFG]
MP26  DC0401012V2B-3T3  [FP-DC0401012V2B_FAN-MFG]
Q15  CSD17571Q2  [DQK0006C]
R117  ValueDisplayed: 2.70  [1206]  (hidden comment: RC1206FR-072R7L)
R118  ValueDisplayed: 2.70  [1206]  (hidden comment: RC1206FR-072R7L)
R119  ValueDisplayed: 2.70  [1206]  (hidden comment: RC1206FR-072R7L)
R120  ValueDisplayed: 2.70  [1206]  (hidden comment: RC1206FR-072R7L)
R121  ValueDisplayed: 2.70  [1206]  (hidden comment: RC1206FR-072R7L)
R122  ValueDisplayed: 2.70  [1206]  (hidden comment: RC1206FR-072R7L)
R123  ValueDisplayed: 2.70  [1206]  (hidden comment: RC1206FR-072R7L)
R124  ValueDisplayed: 2.70  [1206]  (hidden comment: RC1206FR-072R7L)
R125  ValueDisplayed: 2.70  [1206]  (hidden comment: RC1206FR-072R7L)
R126  ValueDisplayed: 2.70  [1206]  (hidden comment: RC1206FR-072R7L)
R127  ValueDisplayed: 2.70  [1206]  (hidden comment: RC1206FR-072R7L)
R128  ValueDisplayed: 2.70  [1206]  (hidden comment: RC1206FR-072R7L)
R129  ValueDisplayed: 10.0k  [0402L]  (hidden comment: CRCW040210K0FKED)
R130  ValueDisplayed: 200  [0402L]  (hidden comment: CRCW0402200RJNED)
R131  ValueDisplayed: 10.0k  [0402L]  (hidden comment: CRCW040210K0FKED)
TP63  5010  [Keystone5010]  (value not drawn)
TP64  5011  [Keystone5011]  (value not drawn)
U13  TMP235A2DBZR  [DBZ0003A-MFG]
ZZ1  This Assembly Note is for PCB labels only  [AssemblyNoteLabel]  (no BOM)
ZZ2  These assemblies are ESD sensitive, ESD precautions shall be observed.  [AssemblyNote]  (no BOM)
ZZ3  These assemblies must be clean and free from flux and all contaminants. Use of no clean flux is not acceptable.  [AssemblyNote]  (no BOM)
ZZ4  These assemblies must comply with workmanship standards IPC-A-610 Class 2, unless otherwise specified.  [AssemblyNote]  (no BOM)

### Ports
FAN_CTRL (bidir), TEMP_SENSE_AMB (bidir)

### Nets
+3V3_Ua2: C104.1 U13.1(VDD)
+12V_FAN: C366.1(+) C367.1(+) C368.1(+) C369.1 C401.1 D6.1(K) J19.1 J20.1 J21.1 TP63.1
GND: C103.2 C104.2 C366.2(-) C367.2(-) C368.2(-) C369.2 C401.2 C417.2 Q15.4(S) Q15.7(S) R131.1 U13.3(GND)  [also labelled GNDP]
VDC_MID: R117.1 R118.1 R119.1 R120.1 R121.1 R122.1 R123.1 R124.1 R125.1 R126.1 R127.1 R128.1
FAN_CTRL: R130.1 ; port FAN_CTRL
FAN_GATE: C417.1 Q15.3(G) R130.2 R131.2
FAN_SN: D6.2(A) J19.2 J20.2 J21.2 Q15.1(D) Q15.2(D) Q15.5(D) Q15.6(D) Q15.8(D) TP64.1
MP1: MP1.1(MNT_1) R117.2 R120.2
MP2: MP2.2(MNT_2) R118.2 R121.2
MP3: MP3.1(MNT_1) R119.2 R122.2
MP4: MP4.2(MNT_2) R123.2 R126.2
MP5: MP5.2(MNT_2) R124.2 R127.2
MP6: MP6.1(MNT_1) R125.2 R128.2
TEMP_SENSE_AMB: C103.1 R129.1 ; port TEMP_SENSE_AMB
NetR129_2: R129.2 U13.2(VOUT)

Not connected (* = marked no-connect by the designer): J19 3; J20 3; J21 3; MP1 2(MNT_2); MP2 1(MNT_1); MP3 2(MNT_2); MP4 1(MNT_1); MP5 1(MNT_1); MP6 2(MNT_2); MP7 1; MP8 1; MP9 1; MP10 1; MP11 1; MP12 1; MP13 1; MP14 1; MP15 1; MP16 1; MP17 1

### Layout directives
net class STAND_OFFS: (no net found under the mark)
net class HV_Heatsink: (no net found under the mark)

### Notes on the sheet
- Fan mount brackets
  35mm spacing for mount
- Variant
- Variant/Label Table
- Label Text
- 001
- 002
- ChangeMe!
- Fan 40 x 40 mm
  T3 config:
  P1+
  P2 -
  P3 Tach

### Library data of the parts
!PCB1 = CMP-0003618-2: Manufacturer: Any; PartNumber: TIDA-01606
C103 C104 C417 = CMP-0006659-2: as C6 on sheet TIDA-1606-Aux-Supply-E7
C366-C368 = CMP-0010339-1: CAP, AL, 100 uF, 25 V, +/- 20%, 0.13 ohm, TH; Manufacturer: Panasonic; TaMin_C: -40°C; ESR_ohm: 0.13; Polarized: Y; SizeAreaWB_mm2: 68.89; U/M: EA; Value: 100uF; TaMax_C: 105°C; SizeZ_mm: 12.7; SizeX_mm: 6.3; Cap_Case: 6.3x11.2; SizeArea_mm2: 39.69; CompType: Capacitor; AEC Qualified: N; Cap_F: 100µF; IRMS_A: 455mA; AEC Category: Q200
C369 = CMP-0006356-2: as C2 on sheet TIDA-1606-Aux-Supply-E7
C401 = CMP-0007121-4: as C17 on sheet TIDA-1606-Aux-Supply-E7
D6 = CMP-0028389-2: Diode, Schottky, 60 V, 1 A, SMA; Manufacturer: Diodes Inc.; Green_Lifecycle: Not Set; SizeAreaWB_mm2: 37.3428; Green_REACh: Incomplete; TJmax_C: 150°C; AEC Category: Q101; SizeZ_mm: 2.87; RJC_CperW: 20; Io_A: 1A; SizeArea_mm2: 16.3228; Vf_V: 700mV; Value2: 0.7V; SizeY_mm: 2.92; Vr_V: 60V; SizeX_mm: 5.59; Value: 60V
FID1-FID3 = CMP-0077181-1: Fiducial mark.  There is nothing to buy or mount.
J19-J21 = CMP-0122568-1: Mini-Latch™ Wire-to-Board Header, Vertical, with Friction Ramp, 3 Circuits, Gold (Au) Plating; Manufacturer: Molex; ContactFinish: Gold,Nickel; Current_A: 3A; Row_Count: 1; Voltage_V: 250V; AEC Qualified: No; Conn Gender: Male; DUT-Pitch_mm: 2.5mm; SizeZ_mm: 12.1mm
LBL1 = CMP-0003625-1: Thermal Transfer Printable Labels, 0.650" W x 0.200" H - 10,000 per roll; Manufacturer: Brady; CompType: Label
Logo1 = CMP-0074844-2: Manufacturer: Texas Instruments; SymbolCreator: a0412235; AEC Category: Q200; CompType: IC
LOGO2 LOGO6 LOGO9-LOGO11 = CMP-0074837-2: IEC 61010-1 Hot Surface Warning; Manufacturer: Texas Instruments; SymbolCreator: a0412235; AEC Category: Q200; CompType: IC
Logo3 = CMP-0074847-1: FCC_disclaimer; Library Reference: Logo
Logo4 = CMP-0074769-4: Manufacturer: Texas Instruments; AEC Category: Q200; CompType: IC
LOGO5 LOGO7 LOGO8 LOGO12 LOGO13 = CMP-0074835-1: IEC 61010-1 High Voltage Warning; SymbolCreator: a0412235; Lib Reference: IEC_HighVoltage
MP1-MP6 = CMP-0121069-1: Heatsink; TO-247; 75 x 20.47 x 38mm; Spring Clip Mount; Manufacturer: Ohmite; AEC Qualified: No
MP7-MP17 = CMP-0121346-1: Manufacturer: Würth Elektronik; AEC Qualified: No; Is Female: yes; SizeZ_mm: 4.1mm
MP18-MP23 = CMP-0122371-1: Manufacturer: Keystone; AEC Qualified: No; SizeZ_mm: 11.76mm
MP24-MP26 = CMP-0122386-3: DC FAN; Manufacturer: Wakefield-Vette; AEC Qualified: No
Q15 = CMP-0000585-1: as Q1 on sheet TIDA-1606-Aux-Supply-E7
R117-R128 = CMP-0018180-2: RES, 2.70, 1%, 0.25 W, 1206; Manufacturer: Yageo America; Power_W: 250mW; TempCo: 200 ppm/C; Value_Code: 2R70; U/M: EA; Value: 2.70; Res_ohm: 2.7; SizeX_mm: 3.2; SizeY_mm: 1.6; SizeZ_mm: 1.35; Value2: 0.25W; SizeArea_mm2: 5.12; VDC_V: 200V; AEC Category: Q200
R129 R131 = CMP-0025958-3: RES, 10.0 k, 1%, 0.063 W, AEC-Q200 Grade 0, 0402; Manufacturer: Vishay-Dale; Power_W: 63mW; TempCo: 100 ppm/C; Value_Code: 10k0; Value: 10.0k; EIA_Code: E96; Res_ohm: 10k; SizeX_mm: 1; SizeY_mm: 0.5; SizeZ_mm: 0.6; Value2: 0.063W; AEC Qualified: Y; VDC_V: 50V; AEC Category: Q200; AEC Grade: 0
R130 = CMP-0026874-3: RES, 200, 5%, 0.063 W, AEC-Q200 Grade 0, 0402; Manufacturer: Vishay-Dale; Power_W: 63mW; TempCo: 200 ppm/C; Value_Code: 200R; Value: 200; EIA_Code: E24; SizeX_mm: 1; SizeY_mm: 0.5; SizeZ_mm: 0.6; Value2: 0.063W; AEC Qualified: Y; VDC_V: 50V; AEC Category: Q200; AEC Grade: 0
TP63 = CMP-0055147-2: as TP1 on sheet TIDA-1606-Aux-Supply-E7
TP64 = CMP-0055148-2: as TP2 on sheet TIDA-1606-Aux-Supply-E7
U13 = CMP-0088337-2: Temperature Sensor Analog, Local -40°C ~ 150°C 10mV/°C SOT-23-3; Manufacturer: Texas Instruments; TaMax_C: +150°C; Max Supply Voltage: 5.5V; CompType: IC; AEC Qualified: No; Operating Supply Current: 9uA; Accuracy: 0.5%; AEC Category: Q200; Min Supply Voltage: 2.3V; Sensor Output: Analog Voltage; Standoff Height: 0.01mm; SizeZ_mm: 1.12mm
ZZ1 = CMP-0003616-3
ZZ2 = CMP-0077236-1
ZZ3 = CMP-0077237-1
ZZ4 = CMP-0077238-1

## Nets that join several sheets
1.65V: TIDA-1606-SW-Current-Measurements-E7 (8 pins), TIDA-1606-Low-Side-E7 (C223.2 R234.2), TIDA-1606-Middle-Side-E7 (C272.2 R270.2), TIDA-1606-Control-Interface-E7 (R396.1 R411.2), TIDA-1606-Aux-Supply-E7 (C20.1 C21.2 TP5.1 U4.1)
3.3VREF: TIDA-1606-PCC-Voltage-Measurements-E7 (R207.2 R225.2 R300.2), TIDA-1606-SW-Voltage-Measurements-E7 (R65.2 R70.2 R75.2), TIDA-1606-Control-Interface-E7 (R304.1), TIDA-1606-Aux-Supply-E7 (R17.1)
+3V3: TIDA-1606-EMI-Protection-E7- (R104.1), TIDA-1606-Switching-Node-L1-E7 (9 pins), TIDA-1606-Switching-Node-L2-E7 (9 pins), TIDA-1606-Switching-Node-L3-E7 (9 pins), TIDA-1606-Low-Side-E7 (15 pins), TIDA-1606-Middle-Side-E7 (9 pins), TIDA-1606-Control-Interface-E7 (11 pins), TIDA-1606-CAN-Communication-E7 (FB17.1), TIDA-1606-Aux-Supply-E7 (C19.1 U5.1)
+3V3_Ua: TIDA-1606-SW-Current-Measurements-E7 (10 pins), TIDA-1606-Low-Side-E7 (L7.2), TIDA-1606-Middle-Side-E7 (L8.1), TIDA-1606-DC-Voltage-Measurements-E7- (6 pins), TIDA-1606-Aux-Supply-E7 (C27.1 U7.1)
+3V3_Ua2: TIDA-1606-SW-Current-Measurements-E7 (8 pins), TIDA-1606-Low-Side-E7 (C450.1 C451.1 U8.8), TIDA-1606-DC-Voltage-Measurements-E7- (C30.1 C31.1 U61.8), TIDA-1606-Aux-Supply-E7 (C484.1 U66.1), TIDA-1606-Hardware-E7 (C104.1 U13.1)
+3V3_Ud: TIDA-1606-PCC-Current-Measurements-E7 (12 pins), TIDA-1606-Aux-Supply-E7 (C24.1 U6.1)
+5V: TIDA-1606-PCC-Voltage-Measurements-E7 (11 pins), TIDA-1606-SW-Voltage-Measurements-E7 (11 pins), TIDA-1606-DC-Voltage-Measurements-E7- (C360.1 L11.2), TIDA-1606-Control-Interface-E7 (8 pins), TIDA-1606-CAN-Communication-E7 (FB16.1), TIDA-1606-Aux-Supply-E7 (14 pins)
+5VISO_DC-: TIDA-1606-Low-Side-E7 (C222.1 U28.1), TIDA-1606-DC-Voltage-Measurements-E7- (11 pins)
+12V: TIDA-1606-EMI-Protection-E7- (7 pins), TIDA-1606-Switching-Node-L1-E7 (C438.1 FB22.1), TIDA-1606-Switching-Node-L2-E7 (C439.1 FB23.1), TIDA-1606-Switching-Node-L3-E7 (C437.1 FB21.1), TIDA-1606-Low-Side-E7 (6 pins), TIDA-1606-Middle-Side-E7 (6 pins), TIDA-1606-Aux-Supply-E7 (C442.1 FB25.2)
+12V_FAN: TIDA-1606-Aux-Supply-E7 (C440.1 FB24.2), TIDA-1606-Hardware-E7 (10 pins)
GND: TIDA-1606-EMI-Protection-E7- (25 pins), TIDA-1606-PCC-Current-Measurements-E7 (16 pins), TIDA-1606-PCC-Voltage-Measurements-E7 (23 pins), TIDA-1606-SW-Voltage-Measurements-E7 (23 pins), TIDA-1606-SW-Current-Measurements-E7 (20 pins), TIDA-1606-Switching-Node-L1-E7 (37 pins), TIDA-1606-Switching-Node-L2-E7 (37 pins), TIDA-1606-Switching-Node-L3-E7 (37 pins), TIDA-1606-Low-Side-E7 (92 pins), TIDA-1606-Middle-Side-E7 (79 pins), TIDA-1606-DC-Voltage-Measurements-E7- (22 pins), TIDA-1606-Control-Interface-E7 (84 pins), TIDA-1606-CAN-Communication-E7 (FB20.1 J23.1), TIDA-1606-Aux-Supply-E7 (72 pins), TIDA-1606-Hardware-E7 (12 pins)
GRID_GND: TIDA-1606-Overview-E7 (J30.1), TIDA-1606-EMI-Protection-E7- (30 pins), TIDA-1606-Aux-Supply-E7 (J6.2)
REF_MID1: TIDA-1606-Overview-E7 (Q5.3), TIDA-1606-Middle-Side-E7 (9 pins)
REF_MID2: TIDA-1606-Overview-E7 (Q7.3), TIDA-1606-Middle-Side-E7 (9 pins)
REF_MID3: TIDA-1606-Overview-E7 (Q9.3), TIDA-1606-Middle-Side-E7 (17 pins)
REF_SN_L1: TIDA-1606-Overview-E7 (Q2.3 Q6.3), TIDA-1606-Switching-Node-L1-E7 (17 pins)
REF_SN_L2: TIDA-1606-Overview-E7 (Q3.3 Q8.3), TIDA-1606-Switching-Node-L2-E7 (17 pins)
REF_SN_L3: TIDA-1606-Overview-E7 (Q4.3 Q10.3), TIDA-1606-Switching-Node-L3-E7 (17 pins)
REF_VDC-1: TIDA-1606-Overview-E7 (Q11.3), TIDA-1606-Low-Side-E7 (15 pins)
REF_VDC-2: TIDA-1606-Overview-E7 (Q12.3), TIDA-1606-Low-Side-E7 (13 pins)
REF_VDC-3: TIDA-1606-Overview-E7 (Q13.3), TIDA-1606-Low-Side-E7 (13 pins)
VDC+: TIDA-1606-Overview-E7 (20 pins), TIDA-1606-Switching-Node-L1-E7 (D15.1 U42.5 U42.6 U42.7), TIDA-1606-Switching-Node-L2-E7 (D17.1 U48.5 U48.6 U48.7), TIDA-1606-Switching-Node-L3-E7 (D8.1 U22.5 U22.6 U22.7), TIDA-1606-DC-Voltage-Measurements-E7- (U24.1)
VDC-: TIDA-1606-Overview-E7 (22 pins), TIDA-1606-Aux-Supply-E7 (J4.2)
VDC-_REF: TIDA-1606-Low-Side-E7 (C222.2 NT9.1 U28.4), TIDA-1606-DC-Voltage-Measurements-E7- (19 pins)
VDC_MID: TIDA-1606-Overview-E7 (36 pins), TIDA-1606-EMI-Protection-E7- (6 pins), TIDA-1606-Aux-Supply-E7 (J5.2), TIDA-1606-Hardware-E7 (12 pins)
VDC_MID_IN: TIDA-1606-Overview-E7 (J15.1 R50.I2 TP66.1), TIDA-1606-DC-Voltage-Measurements-E7- (U63.1)
VIN_PWR: TIDA-1606-CAN-Communication-E7 (J22.1), TIDA-1606-Aux-Supply-E7 (9 pins)
CAN_EN: TIDA-1606-Control-Interface-E7 (R460.2), TIDA-1606-CAN-Communication-E7 (R383.1 U50.8)
CAN_RX: TIDA-1606-Control-Interface-E7 (R452.2), TIDA-1606-CAN-Communication-E7 (U50.5)
CAN_TX: TIDA-1606-Control-Interface-E7 (R458.2), TIDA-1606-CAN-Communication-E7 (U50.3)
DESAT_BOT_L1: TIDA-1606-Overview-E7 (8 pins), TIDA-1606-Low-Side-E7 (D10.1)
DESAT_BOT_L2: TIDA-1606-Overview-E7 (6 pins), TIDA-1606-Low-Side-E7 (D11.1)
DESAT_BOT_L3: TIDA-1606-Overview-E7 (6 pins), TIDA-1606-Low-Side-E7 (D12.1)
EN_DCDC_GATES_BUF: TIDA-1606-Switching-Node-L1-E7 (R448.1), TIDA-1606-Switching-Node-L2-E7 (R450.1), TIDA-1606-Switching-Node-L3-E7 (R364.1), TIDA-1606-Low-Side-E7 (R351.1 R353.1 R446.1), TIDA-1606-Middle-Side-E7 (R361.1 R363.1 R447.1), TIDA-1606-Control-Interface-E7 (5 pins)
FAN_CTRL: TIDA-1606-Control-Interface-E7 (R445.1), TIDA-1606-Hardware-E7 (R130.1)
GATE_BOT_L1: TIDA-1606-Overview-E7 (Q11.4), TIDA-1606-Low-Side-E7 (R82.2 R203.2 R204.2 U25.7)
GATE_BOT_L2: TIDA-1606-Overview-E7 (Q12.4), TIDA-1606-Low-Side-E7 (R83.2 R218.2 R219.2 U26.7)
GATE_BOT_L3: TIDA-1606-Overview-E7 (Q13.4), TIDA-1606-Low-Side-E7 (R84.2 R233.2 R235.2 U27.7)
GATE_MID_L1: TIDA-1606-Overview-E7 (Q5.4), TIDA-1606-Middle-Side-E7 (R85.2 R258.2 U32.7)
GATE_MID_L2: TIDA-1606-Overview-E7 (Q7.4), TIDA-1606-Middle-Side-E7 (R86.2 R262.2 U33.7)
GATE_MID_L3: TIDA-1606-Overview-E7 (Q9.4), TIDA-1606-Middle-Side-E7 (R87.2 R266.2 U34.7)
GATE_MID_SN_L1: TIDA-1606-Overview-E7 (Q6.4), TIDA-1606-Switching-Node-L1-E7 (R93.2 R303.2 U39.7)
GATE_MID_SN_L2: TIDA-1606-Overview-E7 (Q8.4), TIDA-1606-Switching-Node-L2-E7 (R341.2 R350.2 U46.7)
GATE_MID_SN_L3: TIDA-1606-Overview-E7 (Q10.4), TIDA-1606-Switching-Node-L3-E7 (R81.2 R172.2 U20.7)
GATE_TOP_L1: TIDA-1606-Overview-E7 (Q2.4), TIDA-1606-Switching-Node-L1-E7 (R88.2 R294.2 R295.2 U38.7)
GATE_TOP_L2: TIDA-1606-Overview-E7 (Q3.4), TIDA-1606-Switching-Node-L2-E7 (R99.2 R333.2 R334.2 U45.7)
GATE_TOP_L3: TIDA-1606-Overview-E7 (Q4.4), TIDA-1606-Switching-Node-L3-E7 (R80.2 R164.2 R165.2 U19.7)
GATES_FLT_L1: TIDA-1606-Switching-Node-L1-E7 (R290.1 U38.13), TIDA-1606-Low-Side-E7 (R199.1 U25.13), TIDA-1606-Control-Interface-E7 (R463.1)
GATES_FLT_L2: TIDA-1606-Switching-Node-L2-E7 (R329.1 U45.13), TIDA-1606-Low-Side-E7 (R214.1 U26.13), TIDA-1606-Control-Interface-E7 (R462.1)
GATES_FLT_L3: TIDA-1606-Switching-Node-L3-E7 (R160.1 U19.13), TIDA-1606-Low-Side-E7 (R229.1 U27.13), TIDA-1606-Control-Interface-E7 (R459.1)
GATES_RDY: TIDA-1606-Switching-Node-L1-E7 (C479.2 R289.1 U38.12), TIDA-1606-Switching-Node-L2-E7 (C480.2 R328.1 U45.12), TIDA-1606-Switching-Node-L3-E7 (C475.2 R159.1 U19.12), TIDA-1606-Low-Side-E7 (9 pins), TIDA-1606-Control-Interface-E7 (R359.1)
GATES_RST: TIDA-1606-Switching-Node-L1-E7 (R297.1), TIDA-1606-Switching-Node-L2-E7 (R336.1), TIDA-1606-Switching-Node-L3-E7 (R167.1), TIDA-1606-Low-Side-E7 (R206.1 R221.1 R237.1), TIDA-1606-Control-Interface-E7 (R457.1)
I_MID+: TIDA-1606-Overview-E7 (R50.E1), TIDA-1606-Middle-Side-E7 (R271.2)
I_MID-: TIDA-1606-Overview-E7 (R50.E2), TIDA-1606-Middle-Side-E7 (R275.2)
I_NEG_RAIL+: TIDA-1606-Overview-E7 (R60.E1), TIDA-1606-Low-Side-E7 (R238.1)
I_NEG_RAIL-: TIDA-1606-Overview-E7 (R60.E2), TIDA-1606-Low-Side-E7 (NT9.2 R243.1)
I_PCC_L1+: TIDA-1606-EMI-Protection-E7- (R77.E1), TIDA-1606-PCC-Current-Measurements-E7 (FB1.1)
I_PCC_L1-: TIDA-1606-EMI-Protection-E7- (R77.E2), TIDA-1606-PCC-Current-Measurements-E7 (FB2.1 FB3.1)
I_PCC_L2+: TIDA-1606-EMI-Protection-E7- (R78.E1), TIDA-1606-PCC-Current-Measurements-E7 (FB4.1)
I_PCC_L2-: TIDA-1606-EMI-Protection-E7- (R78.E2), TIDA-1606-PCC-Current-Measurements-E7 (FB5.1 FB6.1)
I_PCC_L3+: TIDA-1606-EMI-Protection-E7- (R79.E1), TIDA-1606-PCC-Current-Measurements-E7 (FB7.1)
I_PCC_L3-: TIDA-1606-EMI-Protection-E7- (R79.E2), TIDA-1606-PCC-Current-Measurements-E7 (FB8.1 FB9.1)
I_SENSE_SN_L1: TIDA-1606-SW-Current-Measurements-E7 (R310.2), TIDA-1606-Control-Interface-E7 (S2.2)
I_SENSE_SN_L2: TIDA-1606-SW-Current-Measurements-E7 (C329.1 R347.2), TIDA-1606-Control-Interface-E7 (J26.84)
I_SENSE_SN_L3: TIDA-1606-SW-Current-Measurements-E7 (R180.2), TIDA-1606-Control-Interface-E7 (S1.2)
I_SENSE_VDC_MID: TIDA-1606-Middle-Side-E7 (C274.1 R273.1), TIDA-1606-Control-Interface-E7 (J26.97)
I_SENSE_VDC_NEG: TIDA-1606-Low-Side-E7 (C227.1 R240.2), TIDA-1606-Control-Interface-E7 (J26.95)
I_SN_L1+: TIDA-1606-Overview-E7 (L1.5 L1.6), TIDA-1606-SW-Current-Measurements-E7 (U41.2)
I_SN_L1-: TIDA-1606-EMI-Protection-E7- (C68.2 L4.AI TP35.1), TIDA-1606-SW-Voltage-Measurements-E7 (RN1.4), TIDA-1606-SW-Current-Measurements-E7 (U41.1)
I_SN_L2+: TIDA-1606-Overview-E7 (L2.5 L2.6), TIDA-1606-SW-Current-Measurements-E7 (U47.1)
I_SN_L2-: TIDA-1606-EMI-Protection-E7- (C69.2 L4.AII TP36.1), TIDA-1606-SW-Voltage-Measurements-E7 (RN2.4), TIDA-1606-SW-Current-Measurements-E7 (U47.2)
I_SN_L3+: TIDA-1606-Overview-E7 (L3.5 L3.6), TIDA-1606-SW-Current-Measurements-E7 (U21.1)
I_SN_L3-: TIDA-1606-EMI-Protection-E7- (C70.2 L4.AIII TP37.1), TIDA-1606-SW-Voltage-Measurements-E7 (RN3.4), TIDA-1606-SW-Current-Measurements-E7 (U21.2)
OC_L1: TIDA-1606-SW-Current-Measurements-E7 (R307.2 U41.7), TIDA-1606-Control-Interface-E7 (R470.2)
OC_L2: TIDA-1606-SW-Current-Measurements-E7 (R339.2 U47.7), TIDA-1606-Control-Interface-E7 (R472.2)
OC_L3: TIDA-1606-SW-Current-Measurements-E7 (R177.2 U21.7), TIDA-1606-Control-Interface-E7 (R476.2)
PCC_L1: TIDA-1606-Overview-E7 (J14.1), TIDA-1606-EMI-Protection-E7- (F1.2 TP21.1)
PCC_L2: TIDA-1606-Overview-E7 (J16.1), TIDA-1606-EMI-Protection-E7- (F2.2 TP25.1)
PCC_L3: TIDA-1606-Overview-E7 (J17.1), TIDA-1606-EMI-Protection-E7- (F3.2 TP27.1)
PWM1_BUF_L1: TIDA-1606-Switching-Node-L1-E7 (R246.2), TIDA-1606-Control-Interface-E7 (R101.2)
PWM1_BUF_L2: TIDA-1606-Switching-Node-L2-E7 (R264.2), TIDA-1606-Control-Interface-E7 (R106.2)
PWM1_BUF_L3: TIDA-1606-Switching-Node-L3-E7 (R157.2), TIDA-1606-Control-Interface-E7 (R112.2)
PWM2_BUF_L1: TIDA-1606-Low-Side-E7 (R196.2), TIDA-1606-Control-Interface-E7 (R102.2)
PWM2_BUF_L2: TIDA-1606-Low-Side-E7 (R210.2), TIDA-1606-Control-Interface-E7 (R107.2)
PWM2_BUF_L3: TIDA-1606-Low-Side-E7 (R211.2), TIDA-1606-Control-Interface-E7 (R114.2)
PWM3_BUF_L1: TIDA-1606-Middle-Side-E7 (R224.2), TIDA-1606-Control-Interface-E7 (R103.2)
PWM3_BUF_L2: TIDA-1606-Middle-Side-E7 (R226.2), TIDA-1606-Control-Interface-E7 (R108.2)
PWM3_BUF_L3: TIDA-1606-Middle-Side-E7 (R242.2), TIDA-1606-Control-Interface-E7 (R116.2)
PWM4_BUF_L1: TIDA-1606-Switching-Node-L1-E7 (R260.2), TIDA-1606-Control-Interface-E7 (R105.2)
PWM4_BUF_L2: TIDA-1606-Switching-Node-L2-E7 (R268.2), TIDA-1606-Control-Interface-E7 (R110.2)
PWM4_BUF_L3: TIDA-1606-Switching-Node-L3-E7 (R174.2), TIDA-1606-Control-Interface-E7 (R168.2)
RY_N: TIDA-1606-EMI-Protection-E7- (R113.1), TIDA-1606-Control-Interface-E7 (R465.2)
SD_CLKI_OUT_L1: TIDA-1606-PCC-Current-Measurements-E7 (U14.11), TIDA-1606-Control-Interface-E7 (R140.1 R170.2)
SD_CLKI_OUT_L2: TIDA-1606-PCC-Current-Measurements-E7 (U15.11), TIDA-1606-Control-Interface-E7 (R143.1 R192.2)
SD_CLKI_OUT_L3: TIDA-1606-PCC-Current-Measurements-E7 (U16.11), TIDA-1606-Control-Interface-E7 (R145.1 R209.2)
SD_Data_I_PCC_L1: TIDA-1606-PCC-Current-Measurements-E7 (R133.2), TIDA-1606-Control-Interface-E7 (R469.1)
SD_Data_I_PCC_L2: TIDA-1606-PCC-Current-Measurements-E7 (R135.2), TIDA-1606-Control-Interface-E7 (R475.1)
SD_Data_I_PCC_L3: TIDA-1606-PCC-Current-Measurements-E7 (R138.2), TIDA-1606-Control-Interface-E7 (R478.1)
TEMP_SENSE_AMB: TIDA-1606-Control-Interface-E7 (J26.101), TIDA-1606-Hardware-E7 (C103.1 R129.1)
TEMP_SENSE_L1: TIDA-1606-Switching-Node-L1-E7 (C171.1 R301.2), TIDA-1606-Control-Interface-E7 (J26.109)
TEMP_SENSE_L2: TIDA-1606-Switching-Node-L2-E7 (C317.1 R315.2), TIDA-1606-Control-Interface-E7 (J26.107)
TEMP_SENSE_L3: TIDA-1606-Switching-Node-L3-E7 (C158.1 R182.2), TIDA-1606-Control-Interface-E7 (J26.103)
V_PCC_L1: TIDA-1606-EMI-Protection-E7- (5 pins), TIDA-1606-PCC-Voltage-Measurements-E7 (RN4.4)
V_PCC_L2: TIDA-1606-EMI-Protection-E7- (5 pins), TIDA-1606-PCC-Voltage-Measurements-E7 (RN5.4)
V_PCC_L3: TIDA-1606-EMI-Protection-E7- (5 pins), TIDA-1606-PCC-Voltage-Measurements-E7 (RN6.4)
V_PCC_N: TIDA-1606-EMI-Protection-E7- (5 pins), TIDA-1606-PCC-Voltage-Measurements-E7 (25 pins)
V_SENSE_DC: TIDA-1606-DC-Voltage-Measurements-E7- (R24.2), TIDA-1606-Control-Interface-E7 (S4.2)
V_SENSE_MID_DC-: TIDA-1606-DC-Voltage-Measurements-E7- (R33.2), TIDA-1606-Control-Interface-E7 (S3.2)
V_SENSE_PCC_L1: TIDA-1606-PCC-Voltage-Measurements-E7 (C240.1 R171.2), TIDA-1606-Control-Interface-E7 (J26.106)
V_SENSE_PCC_L2: TIDA-1606-PCC-Voltage-Measurements-E7 (C301.1 R222.2), TIDA-1606-Control-Interface-E7 (J26.90)
V_SENSE_PCC_L3: TIDA-1606-PCC-Voltage-Measurements-E7 (C326.1 R251.2), TIDA-1606-Control-Interface-E7 (J26.93)
V_SENSE_SN_L1: TIDA-1606-SW-Voltage-Measurements-E7 (C61.1 R63.2), TIDA-1606-Control-Interface-E7 (J26.100)
V_SENSE_SN_L2: TIDA-1606-SW-Voltage-Measurements-E7 (C348.1 R68.2), TIDA-1606-Control-Interface-E7 (J26.88)
V_SENSE_SN_L3: TIDA-1606-SW-Voltage-Measurements-E7 (C358.1 R73.2), TIDA-1606-Control-Interface-E7 (J26.91)
V_SN_N: TIDA-1606-EMI-Protection-E7- (11 pins), TIDA-1606-SW-Voltage-Measurements-E7 (25 pins)

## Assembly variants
001: not fitted C181 FID1 FID2 FID3 J4 J5 J23 MP18 MP19 MP20 MP21 MP22 MP23 MP24 MP25 MP26 R31 R36 R104 R189 R355 R384 R387 R411 R427 R436 R438 R439 R444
